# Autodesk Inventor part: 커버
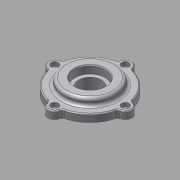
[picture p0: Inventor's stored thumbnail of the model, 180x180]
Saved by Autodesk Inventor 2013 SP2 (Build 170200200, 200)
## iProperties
Company: 한국ATC센터
Created: 2015-12
Part Number: 커버
Document SubType Name: Modeling
Designer: mdu
Density: 2.71 g/cm^3
Material: 알루미늄 6061
Author: mdu
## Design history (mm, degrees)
sketch "스케치1"
  geometry: C1 r 1.621 at (0, 6.75) reference; C2 r 1.621 at (-37, -30.25) reference; C3 r 1.621 at (0, -67.25) reference; C4 r 1.621 at (37, -30.25) reference; C5 r 10 at (0, -30.25) reference; C6 r 12 at (0, -30.25); C7 r 24.5 at (0, -30.25) reference; A1 r 3 centre (-38.77, -20.408) between (-38.239, -23.361) and (-35.862, -21.146) reference; A2 r 7 centre (-37, -30.25) between (-38.239, -23.361) and (-38.239, -37.139) reference; A3 r 3 centre (-38.77, -40.092) between (-35.862, -39.354) and (-38.239, -37.139) reference; A4 r 37 centre (0, -30.25) between (-35.862, -39.354) and (-9.104, -66.113) reference; A5 r 3 centre (-9.842, -69.02) between (-6.889, -68.489) and (-9.104, -66.113) reference; A6 r 7 centre (0, -67.25) between (-6.889, -68.489) and (6.889, -68.489) reference; A7 r 3 centre (9.842, -69.02) between (9.104, -66.112) and (6.889, -68.489) reference; A8 r 37 centre (0, -30.25) between (9.104, -66.112) and (35.863, -39.354) reference; A9 r 3 centre (38.77, -40.092) between (38.239, -37.139) and (35.863, -39.354) reference; A10 r 7 centre (37, -30.25) between (38.239, -37.139) and (38.239, -23.361) reference; A11 r 3 centre (38.77, -20.408) between (35.863, -21.146) and (38.239, -23.361) reference; A12 r 37 centre (0, -30.25) between (35.863, -21.146) and (9.104, 5.612) reference; A13 r 3 centre (9.842, 8.52) between (6.889, 7.989) and (9.104, 5.612) reference; A14 r 7 centre (0, 6.75) between (6.889, 7.989) and (-6.889, 7.989) reference; A15 r 3 centre (-9.842, 8.52) between (-9.104, 5.612) and (-6.889, 7.989) reference; A16 r 37 centre (0, -30.25) between (-9.104, 5.612) and (-35.862, -21.146) reference; 1 further point
  constraints: 1 centre point, 1 coincident
  dimensions: "d2" = 2 radial gap between concentric circles of C6 C5
extrude "돌출1" new body sketch "스케치1" distance "d0" = 8; taper "d1" = 0 deg
sketch "스케치2"
  geometry: C1 r 23.5 at (0, -30.25) reference; C2 r 12 at (0, -30.25) reference; 1 further point
extrude "돌출2" join sketch "스케치2" distance "d4" = 5; taper "d5" = 0 deg
sketch "스케치3"
  geometry: C1 r 23.5 at (0, 0) reference; C2 r 20.5 at (0, 0); 1 further point
  constraints: 1 centre point
  dimensions: "d6" = 3 radial gap between concentric circles of C2 C1
node "작업 평면1"
extrude "돌출3" join sketch "스케치3" stored distance "d7" = 5; taper "d8" = 0 deg
fillet "모깎기1" dims "d9" = 3
sketch "스케치4"
  geometry: C1 r 12 at (0, -30.25) reference; C2 r 27 at (0, -30.25); 1 further point
  constraints: 1 centre point
  dimensions: "d10" = 15 radial gap between concentric circles of C1 C2
extrude "돌출4" join sketch "스케치4" distance "d11" = 7; taper "d12" = 0 deg
fillet "모깎기2" dims "d13" = 3
chamfer "모따기1" distance "d14" = 1; stored, may be unused: second distance "d15" = 2, angle "d16" = 45 deg
node "작업점1"
  node "작업축1"
chamfer "모따기2" distance "d24" = 1; stored, may be unused: second distance "d25" = 2, angle "d26" = 45 deg
hole "구멍6" diameter "d43" = 4.5; stored, may be unused: countersink angle "d47" = 90 deg, drill point angle "d49" = 118 deg; dims "d41" = 10, "d42" = 10, "d44" = 6, "d45" = 8, "d46" = 4.4, "d48" = 8
sketch "스케치8"
  geometry: C1 r 12 at (0, 0) reference; C2 r 16 at (0, 0); 1 further point
  constraints: 1 centre point, 1 coincident
  dimensions: "d53" = 32 diameter of C2
extrude "돌출5" cut sketch "스케치8" distance "d54" = 8.3; taper "d55" = 0 deg
fillet "모깎기3" dims "d56" = 0.3
chamfer "모따기3" distance "d57" = 1.2; stored, may be unused: second distance "d58" = 2, angle "d59" = 30 deg
node "솔리드1"
pattern_circular "원형 패턴1" dims angle "d51" = 360 deg
node "참조1"
node "참조2"
